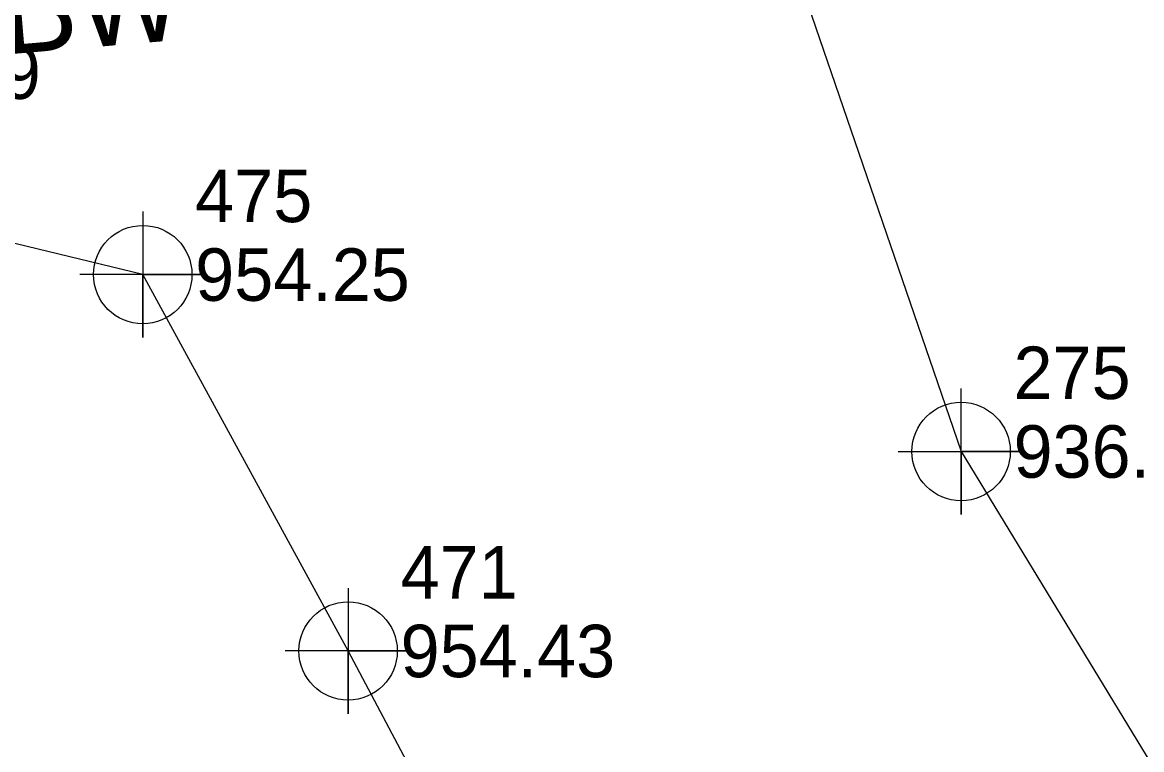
# Model space of a CAD drawing. Extents: x 1150279 to 1151282, y 655434 to 657999.
# Drawn here: x 1150713.8 to 1150767.1, y 657070.4 to 657105.1 of the extents above; entities that cross this region are included whole.
import ezdxf

# ---------------------------------------------------------------- set-up
doc = ezdxf.new("R2010")
doc.units = 0
for name, color, linetype in [('Exist Hydro Jurisdictional Stream or Body of Water', 7, 'Continuous'), ('Exist Hydro Stream or Body of Water Cogo Elevation', 7, 'Continuous'), ('Exist Hydro Stream or Body of Water Cogo Number', 7, 'Continuous'), ('Exist Hydro Stream or Body of Water Cogo Point CELL', 7, 'Continuous'), ('Exist Other Culture Fence Line', 7, 'Continuous'), ('Exist Other Culture Fence Line Cogo Comment', 7, 'Continuous'), ('Exist Other Culture Fence Line Cogo Elevation', 7, 'Continuous'), ('Exist Other Culture Fence Line Cogo Number', 7, 'Continuous'), ('Exist Other Culture Fence Line Cogo Point CELL', 7, 'Continuous'), ('Exist Other Culture Fence Line Text', 7, 'Continuous')]:
    doc.layers.add(name, color=color, linetype=linetype)

msp = doc.modelspace()

# ---------------------------------------------------------------- linework, layer by layer
at = {"layer": 'Exist Hydro Jurisdictional Stream or Body of Water'}
msp.add_lwpolyline([(1150745.794, 657124.778), (1150745.928, 657121.277), (1150758.485, 657084.636), (1150780.666, 657048.192), (1150800.517, 657025.21), (1150816.79, 656993.868)], dxfattribs=at)
at = {"layer": 'Exist Hydro Stream or Body of Water Cogo Point CELL'}
msp.add_lwpolyline([(1150755.485, 657084.636), (1150761.485, 657084.636), (1150758.485, 657084.636), (1150758.485, 657081.636), (1150758.485, 657087.636)], dxfattribs=at)
msp.add_circle((1150758.485, 657084.636), 2.344, dxfattribs=at)
at = {"layer": 'Exist Other Culture Fence Line'}
msp.add_lwpolyline([(1150771.144, 656993.524), (1150752.14, 657032.017), (1150729.275, 657075.13), (1150719.487, 657093.066), (1150693.827, 657099.275)], dxfattribs=at)
at = {"layer": 'Exist Other Culture Fence Line Cogo Point CELL'}
for points in [[(1150719.487, 657096.066), (1150719.487, 657090.066), (1150719.487, 657093.066), (1150722.487, 657093.066), (1150716.487, 657093.066)], [(1150729.275, 657078.13), (1150729.275, 657072.13), (1150729.275, 657075.13), (1150732.275, 657075.13), (1150726.275, 657075.13)]]:
    msp.add_lwpolyline(points, dxfattribs=at)
for centre in [(1150719.487, 657093.066), (1150729.275, 657075.13)]:
    msp.add_circle(centre, 2.344, dxfattribs=at)

# ---------------------------------------------------------------- texts
at = {"layer": 'Exist Hydro Stream or Body of Water Cogo Elevation'}
msp.add_text('936.66', height=2.5, dxfattribs=at).set_placement((1150760.985, 657083.386))
at = {"layer": 'Exist Hydro Stream or Body of Water Cogo Number'}
msp.add_text('275', height=2.5, dxfattribs=at).set_placement((1150760.985, 657087.136))
at = {"layer": 'Exist Other Culture Fence Line Cogo Comment'}
msp.add_text('EL*341028 EL*400519', height=2.5, dxfattribs=at).set_placement((1150680.609, 657101.438))
at = {"layer": 'Exist Other Culture Fence Line Cogo Elevation'}
for s, p in [('954.25', (1150721.987, 657091.816)), ('954.43', (1150731.775, 657073.88))]:
    msp.add_text(s, height=2.5, dxfattribs=at).set_placement(p)
at = {"layer": 'Exist Other Culture Fence Line Cogo Number'}
for s, p in [('475', (1150721.987, 657095.566)), ('471', (1150731.775, 657077.63))]:
    msp.add_text(s, height=2.5, dxfattribs=at).set_placement(p)
at = {"layer": 'Exist Other Culture Fence Line Text'}
msp.add_text('4SBW', height=4, rotation=4.8118, dxfattribs=at).set_placement((1150706.414, 657103.004))

doc.saveas('drawing.dxf')
